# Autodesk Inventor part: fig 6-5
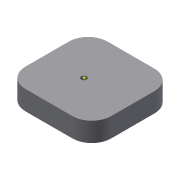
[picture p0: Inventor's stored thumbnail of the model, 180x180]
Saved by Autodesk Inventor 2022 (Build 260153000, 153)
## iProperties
Created: 2004-05
Part Number: fig 6-5
Document SubType Name: Modeling
Designer: CADCIM Technologies
Manufacturer: Standard
Standards Organization: Custom
Density: 1 g/cm^3
Material: Generic
Appearance: Default
Author: CADCIM Technologies
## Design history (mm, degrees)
sketch "Sketch1"
  geometry: L1 (0, 0)-(44.293, 0); L2 (44.293, 0)-(44.293, 42.442); L3 (44.293, 42.442)-(0, 42.442); L4 (0, 42.442)-(0, 0)
  constraints: 8 end point, 2 parallel, 1 horizontal, 1 perpendicular
extrude "Extrusion1" new body sketch "Sketch1" distance "d0" = 10; taper "d1" = 0 deg
fillet "Fillet1" dims "d2" = 10
sketch "Sketch2"
  geometry: 1 further point
sketch "Sketch3"
  geometry: L1 (10, 42.442)-(34.293, 42.442) reference; L2 (0, 10)-(0, 32.442) reference; L3 (34.293, 0)-(10, 0) reference; L4 (44.293, 32.442)-(44.293, 10) reference; A1 r 10 centre (34.293, 32.442) between (44.293, 32.442) and (34.293, 42.442) reference; A2 r 10 centre (10, 32.442) between (10, 42.442) and (0, 32.442) reference; A3 r 10 centre (10, 10) between (0, 10) and (10, 0) reference; A4 r 10 centre (34.293, 10) between (34.293, 0) and (44.293, 10) reference; 1 further point
workaxis "Work Axis1"
  workpoint "Work Point1"
hole "Hole4" diameter "d33" = 3; stored, may be unused: countersink angle "d37" = 90 deg, drill point angle "d39" = 20 deg; dims "d31" = 10, "d32" = 10, "d34" = 12.24, "d35" = 4, "d36" = 2, "d38" = 21.311
body "Solid1"
